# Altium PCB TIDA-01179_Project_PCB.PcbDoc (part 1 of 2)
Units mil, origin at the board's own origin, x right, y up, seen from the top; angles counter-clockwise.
Board outline 3149.61 x 2755.91 mil, 4 copper layers (Top Layer, 2nd Layer, 3rd layer, Bottom Layer), stack 51.6 mil thick; 141 components, 52 nets, 310 pads, 228 vias.
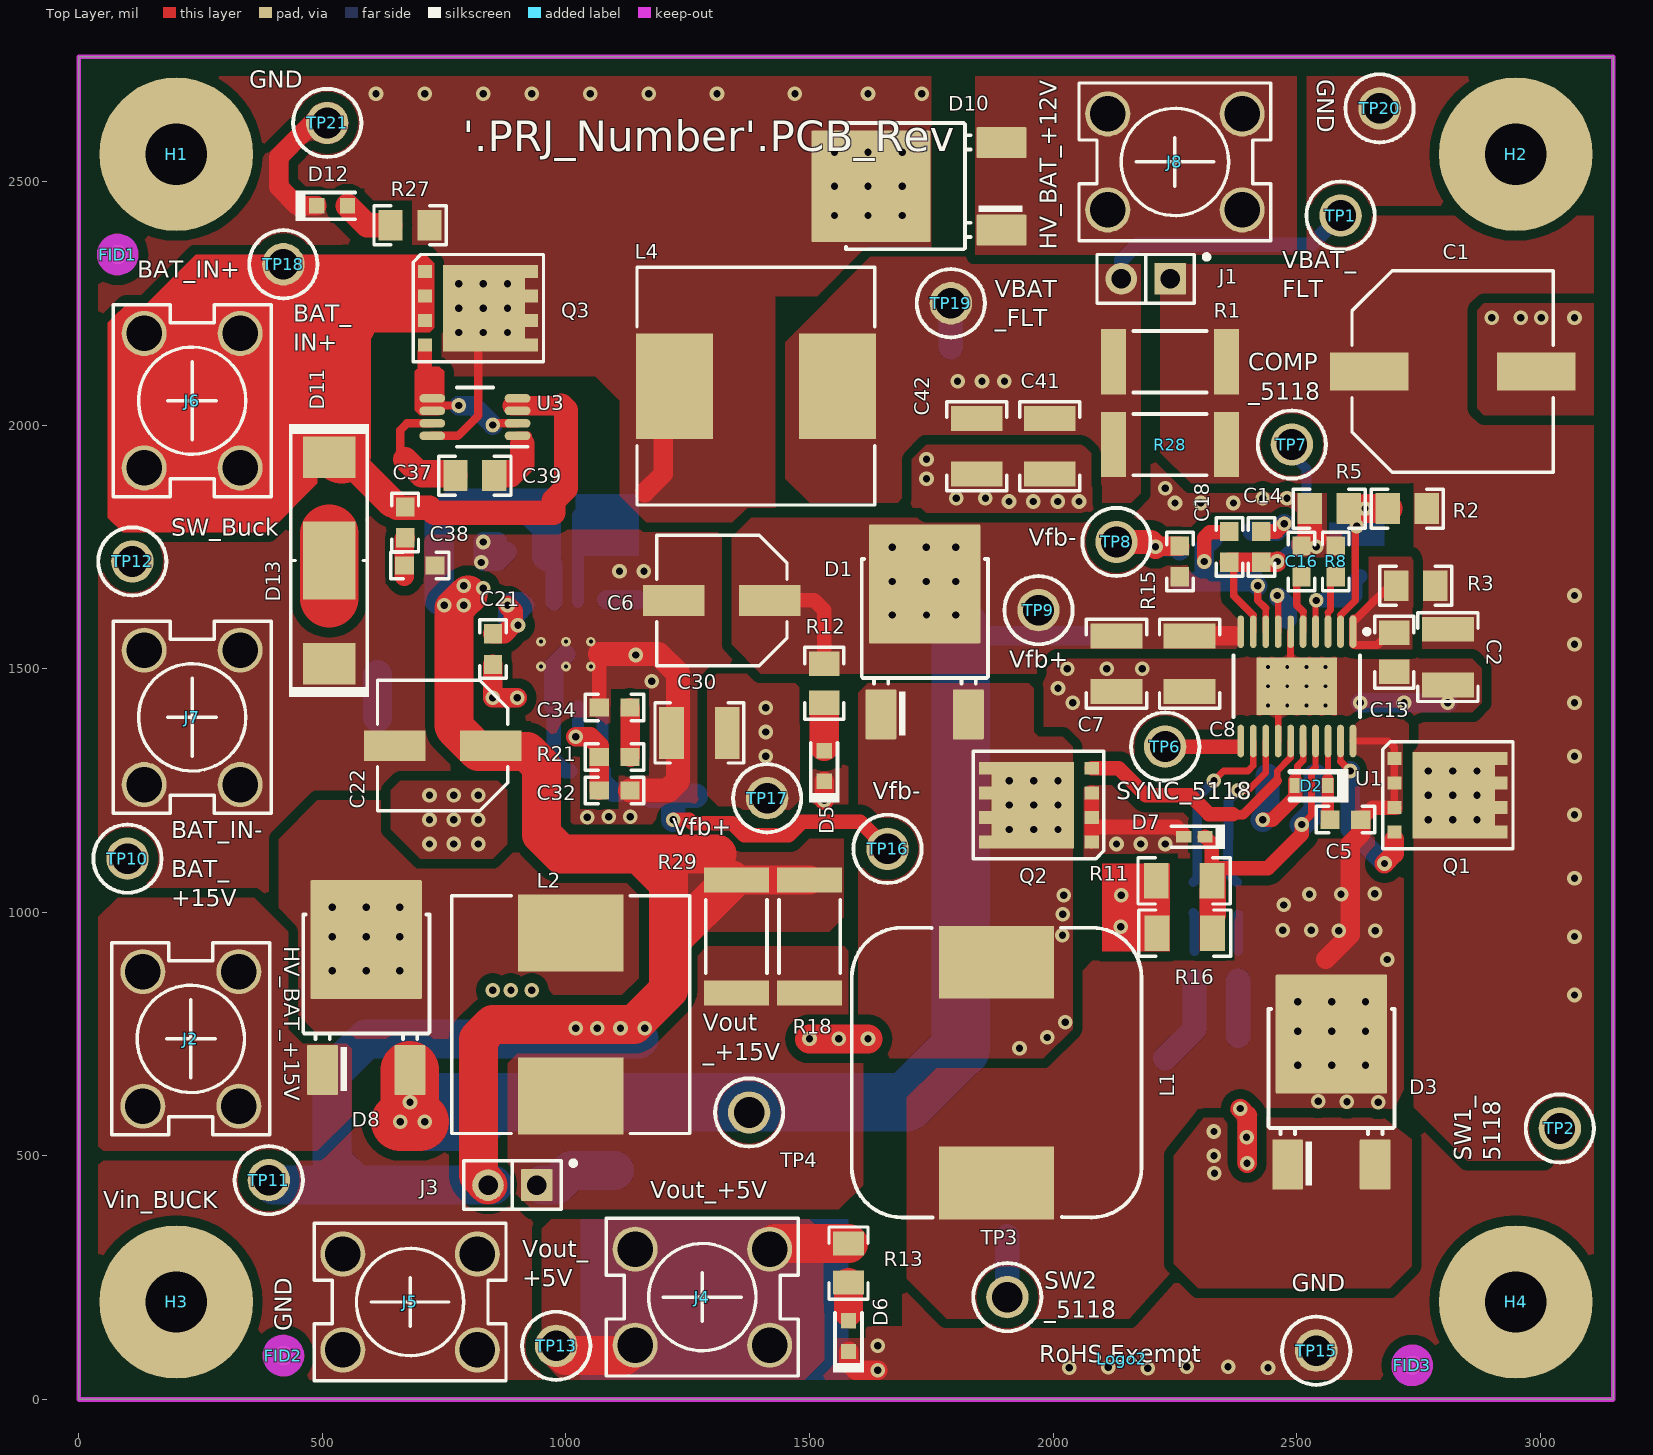
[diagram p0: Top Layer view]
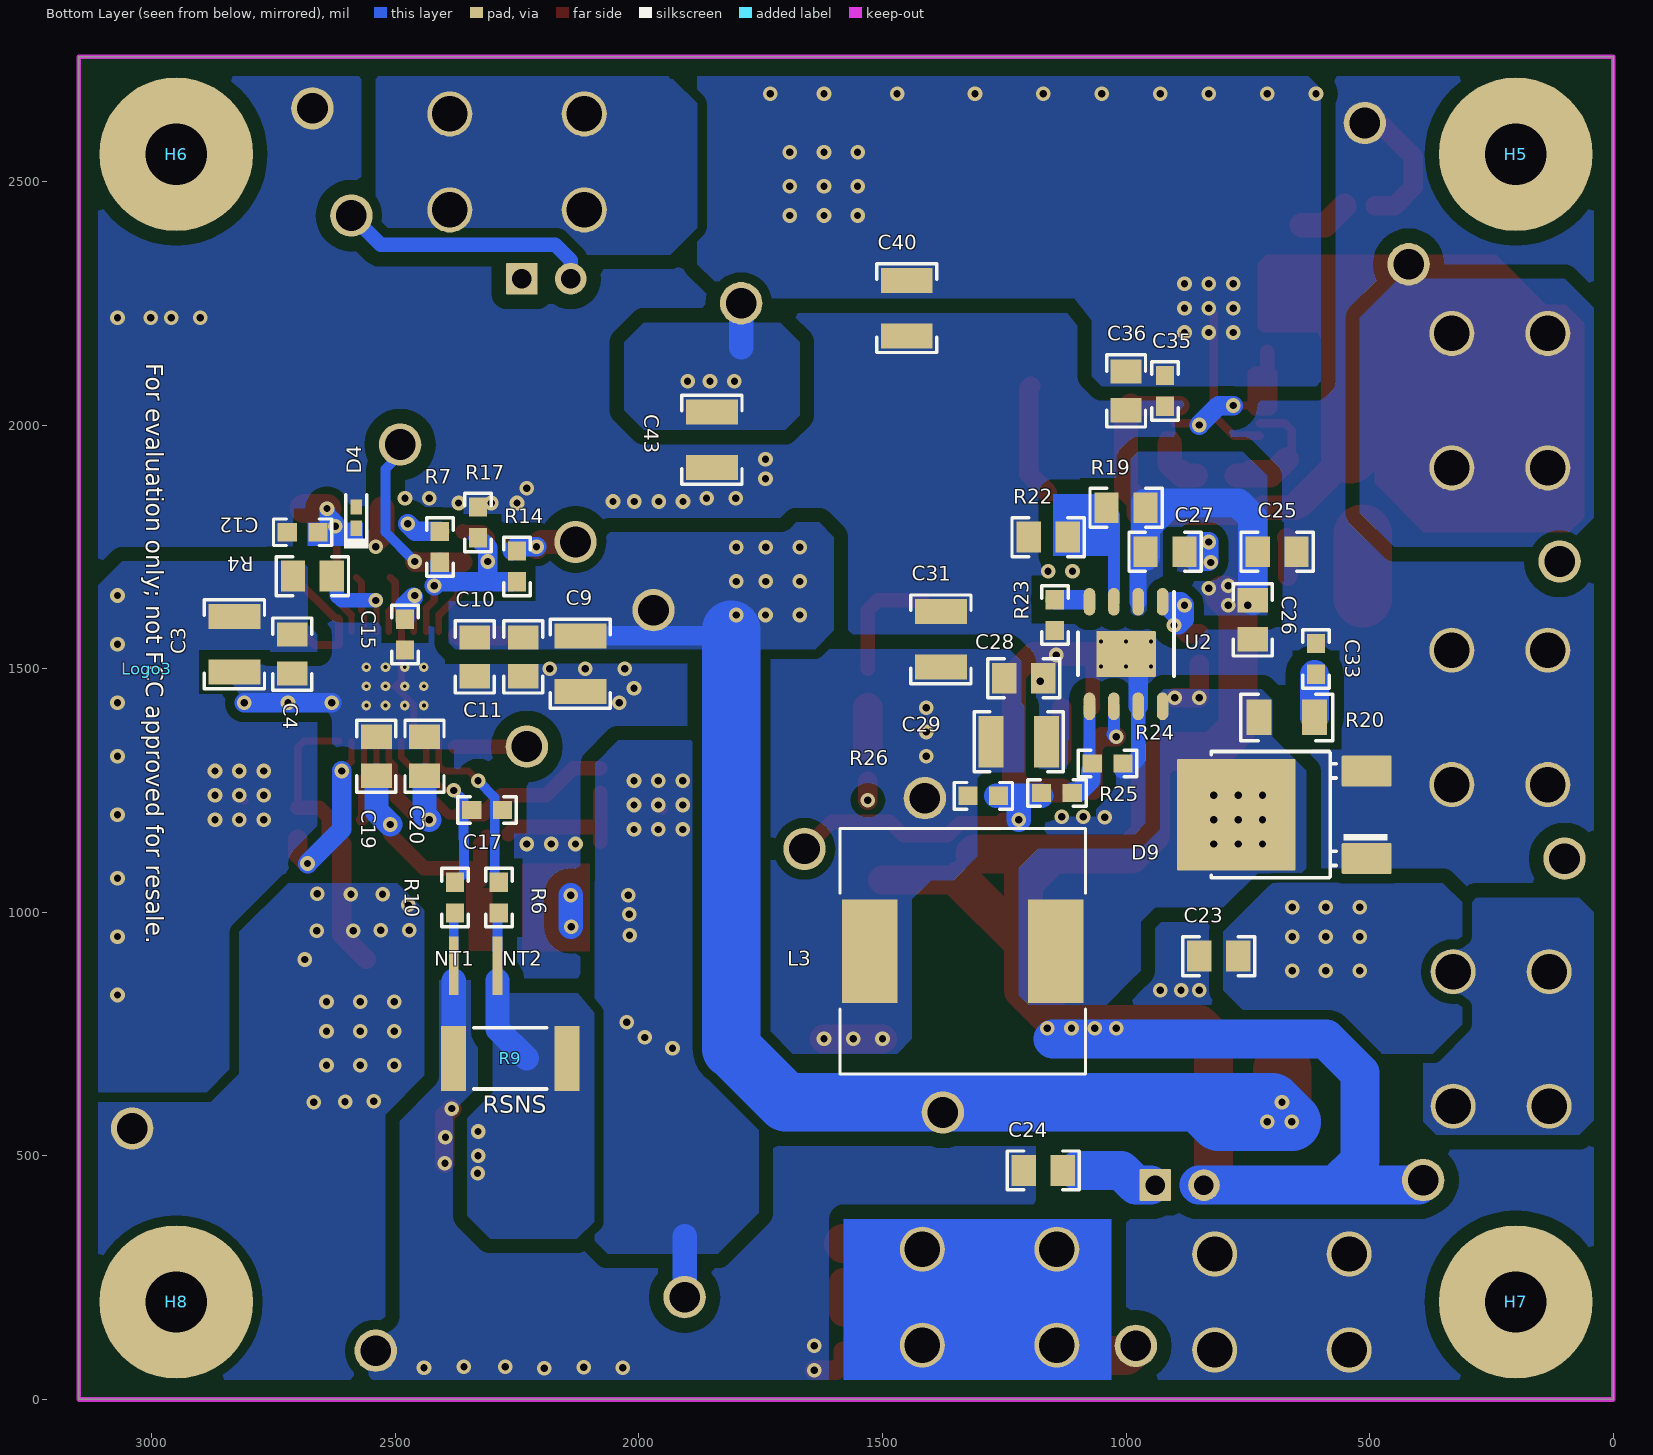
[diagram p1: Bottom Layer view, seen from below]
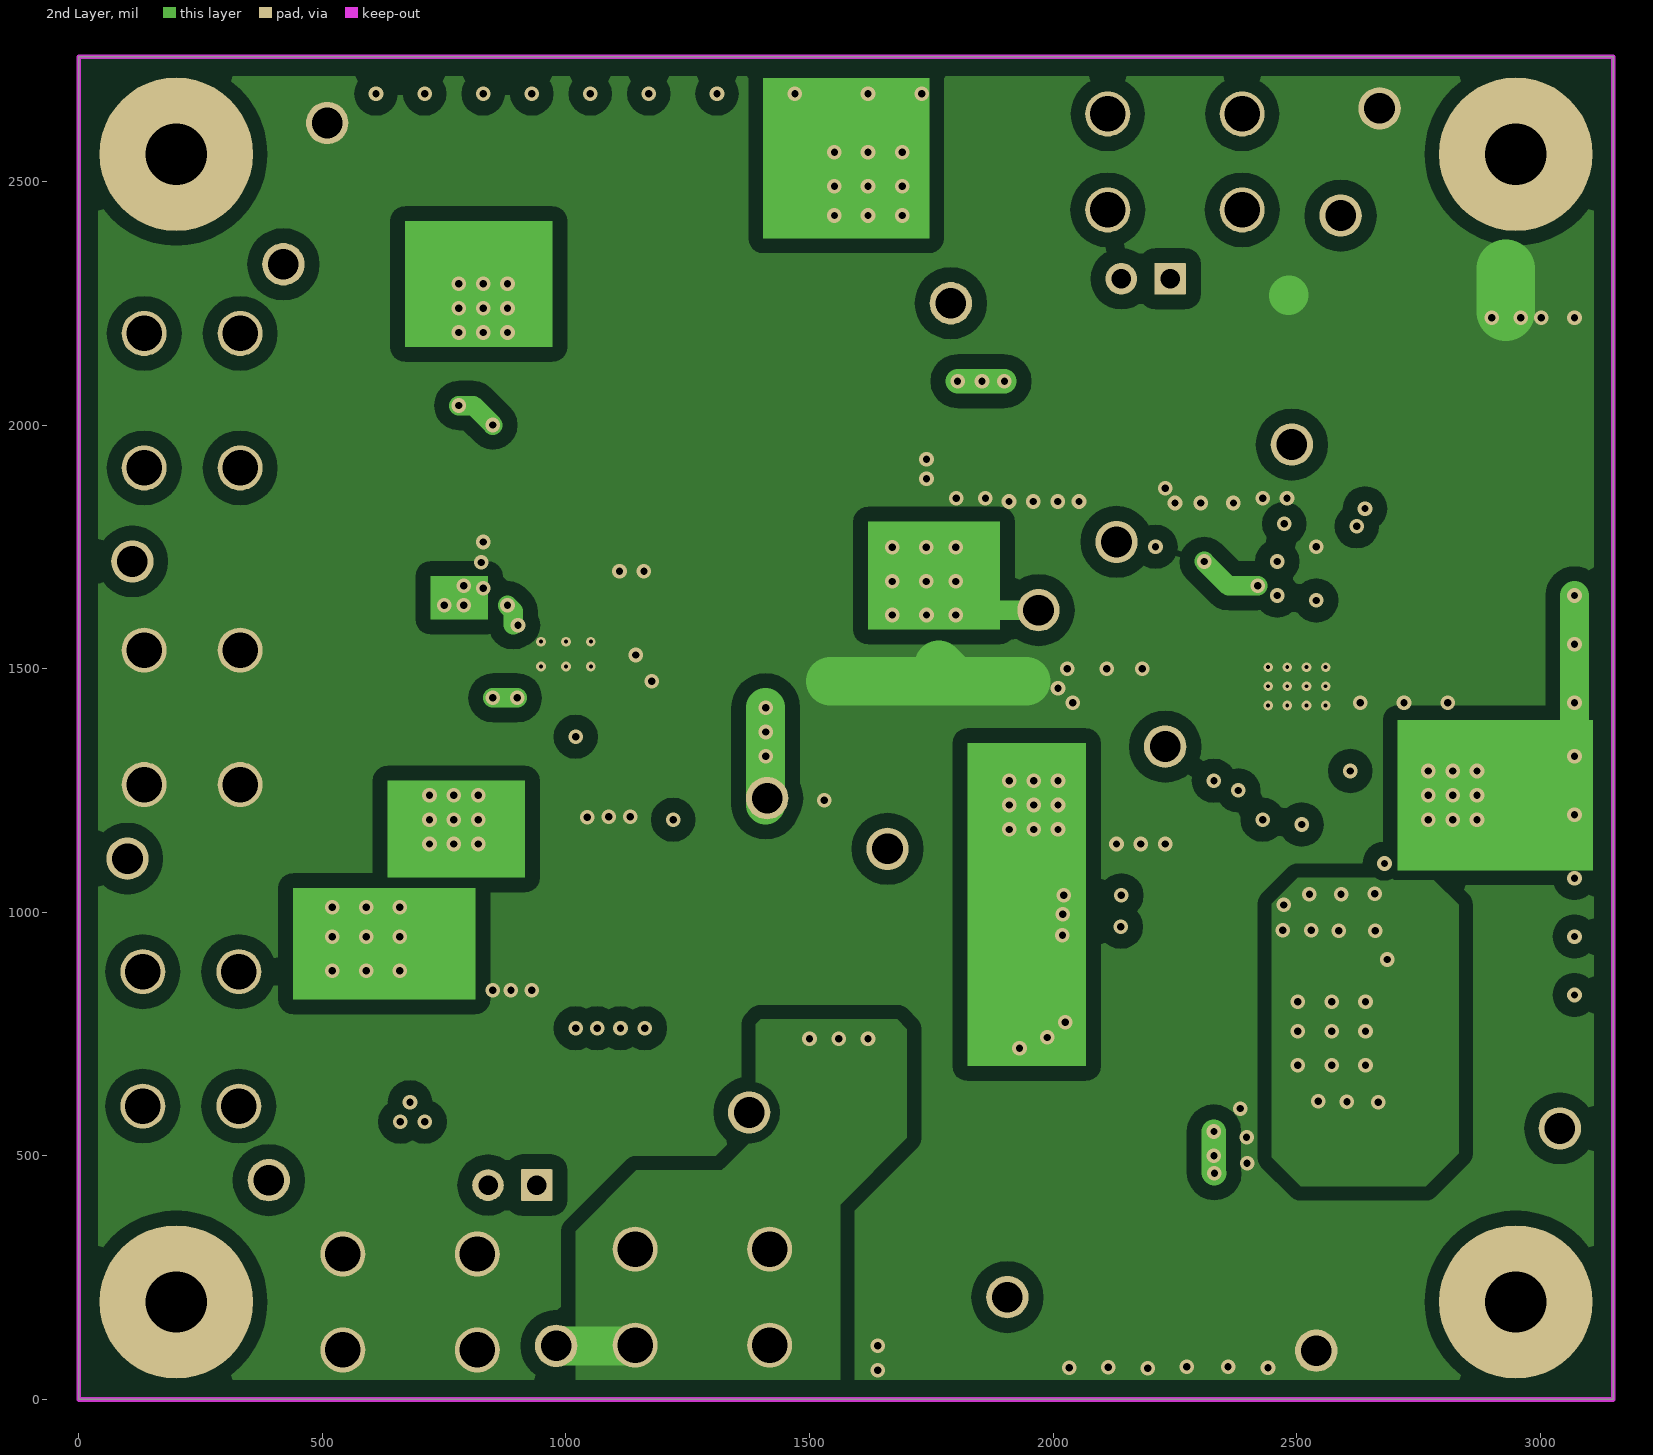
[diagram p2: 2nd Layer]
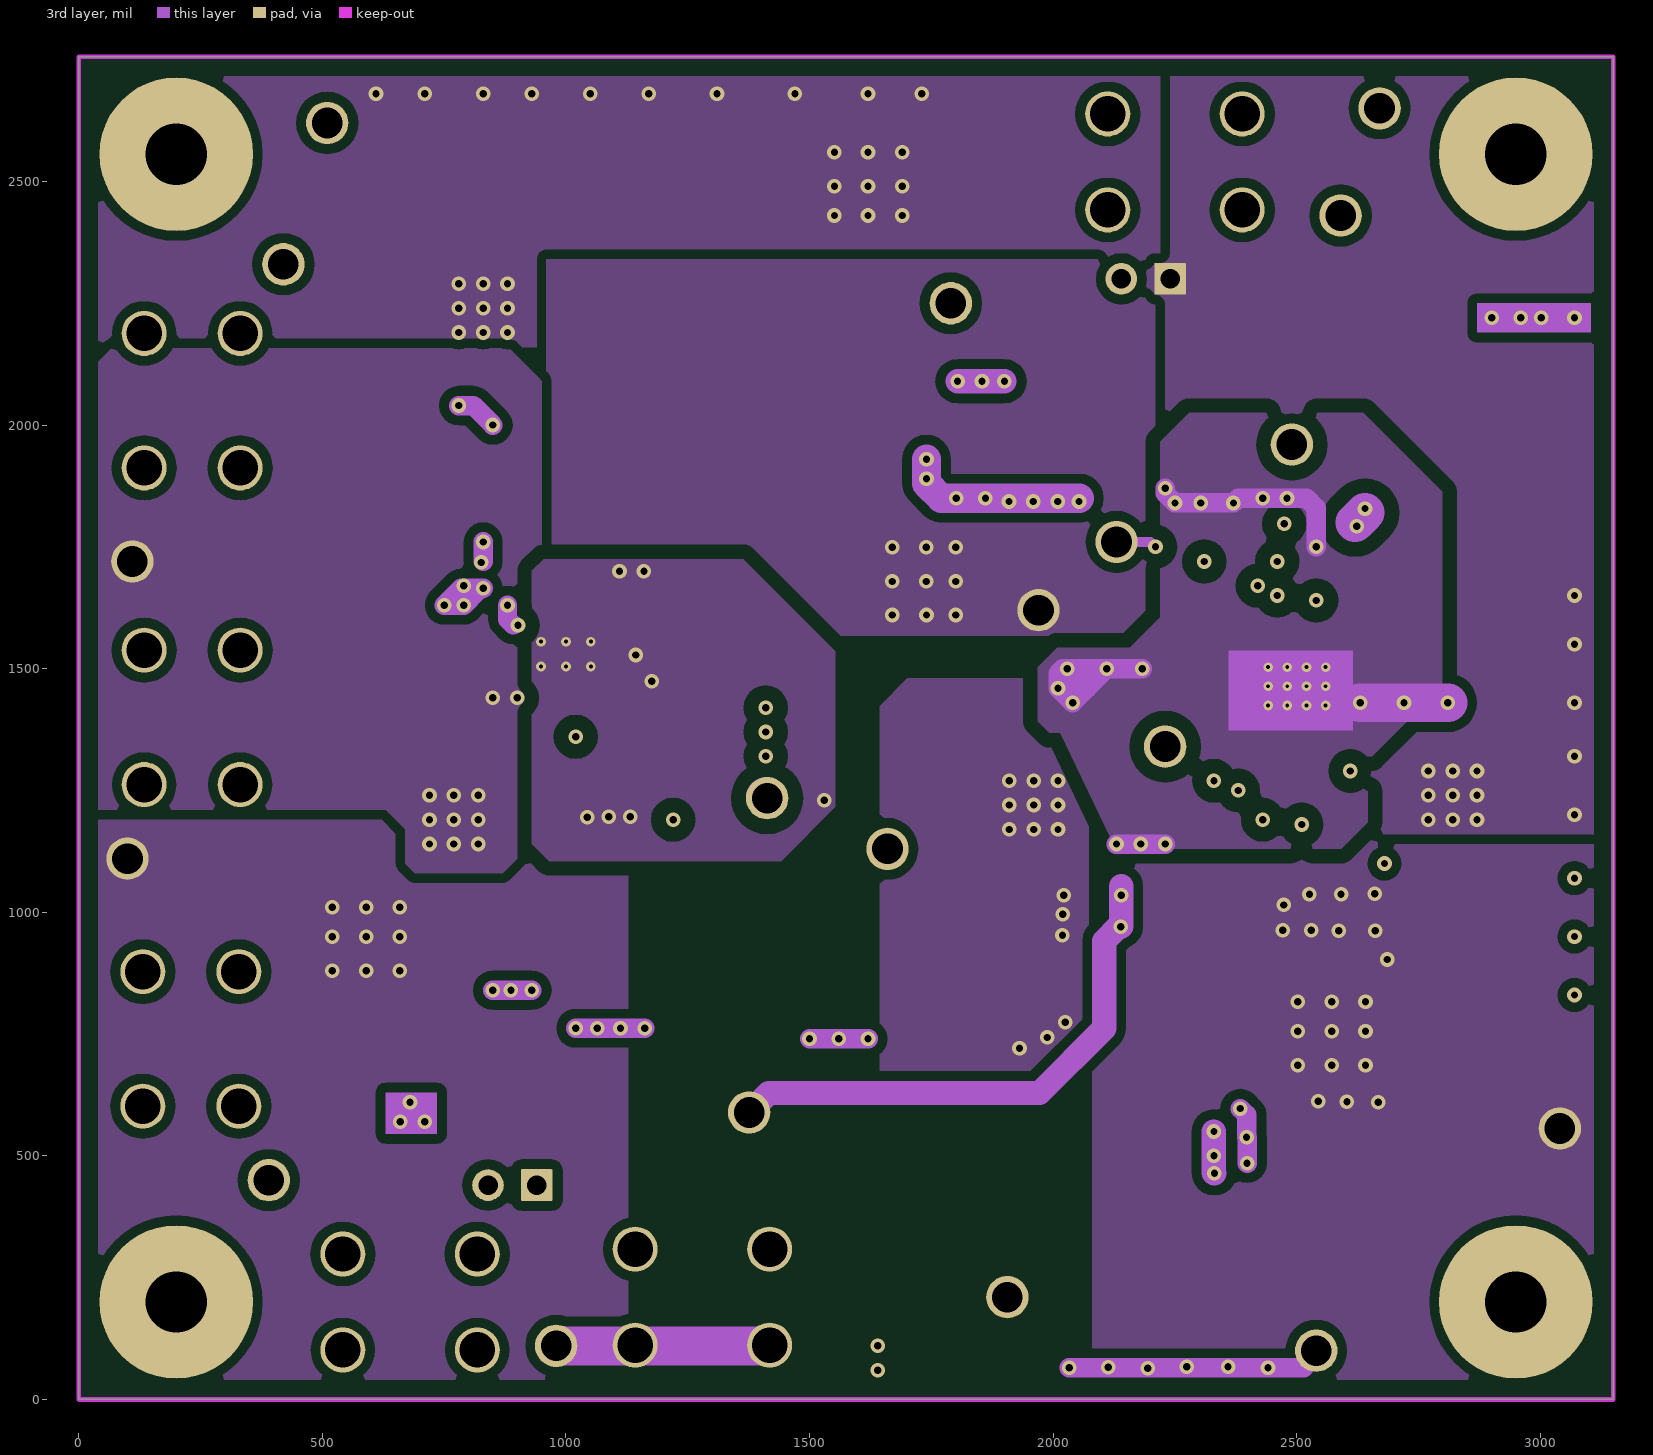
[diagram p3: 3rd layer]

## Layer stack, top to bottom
Top Solder: solder mask 0.4, Solder Resist, Dk 3.5
Top Layer: signal copper 1.4
Dielectric1: prepreg 5, FR-4, Dk 4.2
2nd Layer: signal copper 1.4
Dielectric 2: core 36, FR-4, Dk 4.2
3rd layer: signal copper 1.4
Dielectric 3: prepreg 5, FR-4, Dk 4.2
Bottom Layer: signal copper 1.4
Bottom Solder: solder mask 0.4, Solder Resist, Dk 3.5

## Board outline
0,0 3149.61,0 3149.61,2755.91 0,2755.91

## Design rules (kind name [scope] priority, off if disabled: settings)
AcuteAngle [All] p1: minimum=4.50000000000000E+0001 checktracksonly=FALSE
AssemblyTestPointUsage [All] p1: valid=2
BoardOutlineClearance BoardOutlineClearance_MountingHoles [OnCopper and InComponentClass('Mounting Holes')] p1: gap=40
BoardOutlineClearance BoardOutlineClearance_Poly [OnCopper and InPoly] p2: gap=15
BoardOutlineClearance [OnCopper and Not InComponentClass('Logo') and not InComponentClass('FiducialMark') and not InRegion(1000,500,4000,800)] p3: gap=40
Clearance Clearance_GNDPoly [(InNamedPolygon('2ND_LAYER_GND_P304') OR InNamedPolygon('3RD_LAYER_GND_P231') OR InNamedPolygon('3RD_LAYER_GND_P233') OR InNamedPolygon('BOTTOM_LAYER_GND_P240') OR InNamedPolygon('BOTTOM_LAYER_GND_P300'))] p1: gap=30
Clearance Clearance_Keepouts [((IsTrack Or IsArc) And Not InPoly) And IsFree and IsKeepOut vs ((IsTrack Or IsArc) And Not InPoly) And IsFree and IsKeepOut] p2: gap=0
Clearance Clearance_Poly [InPolygon] p3: gap=20
Clearance [All] p4: gap=7.5
ComponentClearance ComponentClearance_MountingHoles_FiducialMarks [InComponentClass('Mounting Holes') vs InComponentClass('FiducialMark')] p1: gap=50 collisioncheckmode=3 verticalgap=10 showdistances=FALSE
ComponentClearance ComponentClearance_Shunt [InComponentClass('Header') vs InComponentClass('Shunt')] p2: gap=0 collisioncheckmode=3 verticalgap=0 showdistances=FALSE
ComponentClearance ComponentClearance_Logo [InComponentClass('Logo')] p3: gap=50 collisioncheckmode=3 verticalgap=10 showdistances=FALSE
ComponentClearance ComponentClearance_ScrewToNut [(HasFootprint('NY PMS 440 0025 PH')) vs (HasFootprint('Keystone_1902C'))] p4: gap=5 collisioncheckmode=3 verticalgap=10 showdistances=FALSE
ComponentClearance ComponentClearance_MountingHoles [InComponentClass('Mounting Holes')] p5: gap=100 collisioncheckmode=3 verticalgap=100000 showdistances=FALSE
ComponentClearance ComponentClearance_SmallPassives [HasFootprint('0201*') or HasFootprint('0402*') or HasFootprint('0508') or HasFootprint('0603*') or HasFootprint('0612') or HasFootprint('0805*') or HasFootprint('0815*') or HasFootprint('0830*') or HasFootprint('1206*') or HasFootprint('1210*') or HasFootprint('1808*') or HasFootprint('1812*') or HasFootprint('1825*') or HasFootprint('2010*') or HasFootprint('2220*') or HasFootprint('2225*') or HasFootprint('2512*') or HasFootprint('2728*') or HasFootprint('3518*') vs HasFootprint('0201*') or HasFootprint('0402*') or HasFootprint('0508') or HasFootprint('0603*') or HasFootprint('0612') or HasFootprint('0805*') or HasFootprint('0815*') or HasFootprint('0830*') or HasFootprint('1206*') or HasFootprint('1210*') or HasFootprint('1808*') or HasFootprint('1812*') or HasFootprint('1825*') or HasFootprint('2010*') or HasFootprint('2220*') or HasFootprint('2225*') or HasFootprint('2512*') or HasFootprint('2728*') or HasFootprint('3518*')] p6: gap=14.96 collisioncheckmode=3 verticalgap=10 showdistances=FALSE
ComponentClearance ComponentClearance_THtoSMT [IsThruComponent vs IsSMTComponent] p7: gap=40 collisioncheckmode=3 verticalgap=30 showdistances=FALSE
ComponentClearance ComponentClearance_THtoTH [IsThruComponent vs IsThruComponent] p8: gap=30 collisioncheckmode=3 verticalgap=30 showdistances=FALSE
ComponentClearance [All] p9: gap=30 collisioncheckmode=3 verticalgap=10 showdistances=FALSE
DiffPairsRouting [All] p1: maxlimit=100 minlimit=10 mostfreqgap=10 toplayer_minwidth=15 toplayer_maxwidth=15 toplayer_prefwidth=15 midlayer1_minwidth=15 midlayer1_maxwidth=15 midlayer1_prefwidth=15 midlayer2_minwidth=15 midlayer2_maxwidth=15 midlayer2_prefwidth=15 bottomlayer_minwidth=15 bottomlayer_maxwidth=15 bottomlayer_prefwidth=15 maxuncoupledlength=1000
FabricationTestPointUsage TestPointUsage [All] p1: valid=2 allowmultiple=FALSE
FabricationTestpoint Testpoint [All] p1: side=3 testpointundercomponent=TRUE minsize=40 maxsize=100 preferedsize=60 minholesize=0 maxholesize=40 preferedholesize=32 testpointgrid=1 allowsidetop=TRUE allowsidebottom=TRUE usegrid=TRUE gridtolerance=0.01
FanoutControl Fanout_LCC [IsLCC] p1: bgadir=Out bgaviamode=Centered fanoutstyle=Auto fanoutdirection=Alternating viagrid=1 // Fanout_LCC (Default Rule)
FanoutControl Fanout_BGA [IsBGA] p2: bgadir=Out bgaviamode=Centered fanoutstyle=Auto fanoutdirection=Alternating viagrid=1 // Fanout_BGA (Default Rule)
FanoutControl Fanout_Default [All] p4: bgadir=Out bgaviamode=Centered fanoutstyle=Auto fanoutdirection=Alternating viagrid=1 // Fanout_Default (Default Rule)
FanoutControl Fanout_Small [(CompPinCount < 5)] p5: bgadir=Out bgaviamode=Centered fanoutstyle=Auto fanoutdirection=OutThenIn viagrid=1 // Fanout_Small (Default Rule)
HoleSize [All] p1: absolutevalues=TRUE maxlimit=251 minlimit=7.87 maxpercent=80.000 minpercent=20.000
MinimumAnnularRing MinimumAnnularRing_ThermalPadVias [IsVia and InAnyComponent] p1: minimumring=5.91
MinimumAnnularRing [All] p2: minimumring=7
MinimumSolderMaskSliver MinimumSolderMaskSliver_Via [IsVia] p1: minsoldermaskwidth=1.97
MinimumSolderMaskSliver MinimumSolderMaskSliver_Logo [InComponentClass('Logo') vs InComponentClass('Logo')] p2: minsoldermaskwidth=0.7
MinimumSolderMaskSliver [All] p3: minsoldermaskwidth=3.94
PlaneConnect [All] p1: planeconnectstyle=Direct reliefexpansion=10 reliefentries=4 reliefconductorwidth=10 reliefairgap=10
PolygonConnect [All] p1: connectstyle=Direct reliefconductorwidth=10 reliefentries=4 polygonreliefangle="90 Angle" airgapwidth=10
RoutingVias ThermalPadVias [IsVia and InAnyComponent] p1: holewidth=7.87 width=19.68 viastyle="Through Hole" minholewidth=7.87 minwidth=19.68 maxholewidth=12.99 maxwidth=23.62
RoutingVias [All] p2: holewidth=10 width=20 viastyle="Through Hole" minholewidth=7.87 minwidth=5 maxholewidth=40 maxwidth=65
SilkToBoardRegionClearance [Not ((IsComment or IsDesignator) And (Hide <> 'False')) and not InRegion(1000,500,4000,800)] p1:
SilkToSilkClearance SilkToSilkClearance_Pb-FreeLogo [(HasFootprint('Pb-Free_Overlay_Medium') OR HasFootprint('Pb-Free_Overlay_Small')) vs (HasFootprint('Pb-Free_Overlay_Medium') OR HasFootprint('Pb-Free_Overlay_Small'))] p1: silktosilkclearance=0
SilkToSilkClearance [All] p2: silktosilkclearance=4
SilkToSolderMaskClearance SilkToSolderMaskClearance_Via [IsVia] p1: minsilkscreentomaskgap=0 clearancetoexposedcopper=TRUE
SilkToSolderMaskClearance SilkToComponentPadClearance [IsPad and InAnycomponent] p2: minsilkscreentomaskgap=5 clearancetoexposedcopper=TRUE
SilkToSolderMaskClearance "Silk to Solder Mask Opening" [All] p3: minsilkscreentomaskgap=4 clearancetoexposedcopper=FALSE
SolderMaskExpansion SolderMaskExpansion_Vias [IsVia] p1: expansion=-20
SolderMaskExpansion [All] p2: expansion=1.97
Width [All] p1: maxlimit=200 minlimit=6 preferedwidth=10 checkconnectedcopper=TRUE
15 further rules are at their usual default settings.

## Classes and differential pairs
component class AssemblyNote: ZZ1 ZZ2 ZZ3 ZZ4
component class FiducialMark: FID1 FID2 FID3
component class TIDA-01179_Hardware: FID1 FID2 FID3 H1 H2 H3 H4 H5 H6 H7 H8 Logo2 Logo3 ZZ1 ZZ2 ZZ3 ZZ4
component class "Mounting Holes": H1 H2 H3 H4
component class Header: J1 J3
component class TIDA-01179_DCDC_Converters: C1 C2 C3 C4 C5 C6 C7 C8 C9 C10 C11 C12 C13 C14 C15 C16 C17 C18 C19 C20 C21 C22 C23 C24 C25 C26 C27 C28 C29 C30 C31 C32 C33 C34 D1 D2 D3 D4 D5 D6 D7 D8 D9 J1 J2 J3 J4 J5 L1 L2 L3 NT1 NT2 Q1 Q2 R1 R2 R3 R4 R5 R6 R7 R8 R9 R10 R11 R12 R13 R14 R15 R16 R17 R18 R19 R20 R21 R22 R23 R24 R25 R26 R28 R29 TP1 TP2 TP3 TP4 TP6 TP7 TP8 TP9 TP10 TP11 TP12 TP13 TP15 TP16 TP17 U1 U2
component class TIDA-01179_Reverse_Polarity_Protection: C35 C36 C37 C38 C39 C40 C41 C42 C43 COMP D10 D11 D12 D13 GND J6 J7 J8 L4 Q3 R27 TP18 TP19 TP20 TP21 U3

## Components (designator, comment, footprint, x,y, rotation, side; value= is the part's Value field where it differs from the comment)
C1 "EEE-FK1H151P" SM_RADIAL_G 2820,2110 r0 top
C2 "GRM32DR71H335KA88L" 1210_220 2810.24,1523.7 r270 top
C3 "GRM32DR71H335KA88L" 1210_220 2830,1550 r270 bottom
C4 "GRM219R71H333KA01D" 0805_HV 2711.46,1530 r270 bottom
C5 "GRM188R71E104KA01D" 0603 2600,1190 r0 top
C6 "EEE-FK1V101XP" SM_RADIAL_D8 1320,1640 r180 top
C7 "GRM32ER71E226KE15L" 1210_270 2130,1510 r270 top
C8 "GRM32ER71E226KE15L" 1210_270 2280,1510 r270 top
C9 "GRM32ER71E226KE15L" 1210_270 2120,1510 r270 bottom
C10 "GRM219R71E224KA01D" 0805_HV 2337.05,1524.02 r270 bottom
C11 "GRM219R71E224KA01D" 0805_HV 2237.05,1524.02 r270 bottom
C12 "GRM188R71E104KA01D" 0603 2690,1780 r0 bottom
C13 "GRM21BR71H104KA01L" 0805_HV 2700.24,1533.7 r270 top
C14 "GRM188R71E184KA88D" 0603 2427.24,1750 r270 top
C15 "GRM188R71E104KA01D" 0603 2480,1570 r270 bottom
C16 "GRM188R71H391KA01D" 0603 2510,1720 r90 top
C17 "GRM1885C1H101JA01D" 0603 2311.46,1210 r0 bottom
C18 "GCM1885C1H471JA16D" 0603 2361.57,1750 r270 top
C19 "GRM21BR71E105KA99L" 0805_HV 2538.62,1320 r90 bottom
C20 "GRM21BR71E105KA99L" 0805_HV 2440,1320 r90 bottom
C21 "GRM188R71E104KA01D" 0603 850,1540 r90 top
C22 "EEE-FK1V470P" SM_RADIAL_D 747,1342 r180 top
C23 "GRM21BZ71E106KE15L" 0805_HV 810,910 r0 bottom
C24 "GRM21BZ71E106KE15L" 0805_HV 1170,470 r0 bottom
C25 "GRM21BR71E475KA73L" 0805_HV 690,1740 r180 bottom
C26 "GRM21BR71E475KA73L" 0805_HV 740,1600 r270 bottom
C27 "GRM219R71E473KA01D" 0805_HV 920,1740 r180 bottom
C28 "GRM219R71E473KA01D" 0805_HV 1210,1480 r180 bottom
C29 "GRM32ER61C476ME15L" 1210_270 1220,1350 r180 bottom
C30 "GRM32ER61C476ME15L" 1210_270 1274,1368 r180 top
C31 "GRM32ER61C476ME15L" 1210_270 1380,1560 r90 bottom
C32 "GRM1885C1H470JA01D" 0603 1100,1250 r0 top
C33 "GRM188R71H681KA01D" 0603 610,1520 r90 bottom
C34 "GCM188R71H472KA37D" 0603 1100,1420 r180 top
C35 "GRM188R71H104KA93D" 0603 920,2070 r270 bottom
C36 "GRM21BR71H105KA12L" 0805_HV 1000,2070 r270 bottom
C37 "GRM188R71H104KA93D" 0603 670,1800 r270 top
C38 "GRM188R71H104KA93D" 0603 700,1711.46 r0 top
C39 "C2012X7R1H225K125AC" 0805_HV 813.15,1896.3 r0 top
C40 "GRM32ER71H106KA12L" 1210_270 1450,2240 r270 bottom
C41 "GRM32ER71H106KA12L" 1210_270 1993.15,1956.3 r270 top
C42 "GRM32ER71H106KA12L" 1210_270 1843.15,1956.3 r270 top
C43 "GRM32ER71H106KA12L" 1210_270 1850,1970 r270 bottom
D1 "12CWQ06FNPBF" DPAK 1736.3,1540 r90 top
D2 "CDBU0245" SOD-523F 2530,1260 r180 top
D3 "VS-12CWQ10FNPBF" DPAK 2571,616 r90 top
D4 "BZT52C12T-7" SOD-523 2580,1810 r90 bottom
D5 "150060GS75000" WL-SMCW_GREEN 1530,1300 r90 top
D6 "150060GS75000" WL-SMCW_GREEN 1580,130 r90 top
D7 "BZT52C12T-7" SOD-523 2290,1154.57 r180 top
D8 "12CWQ04FNPBF" DPAK 590,810 r90 top
D9 "MBRD835LT4G" DPAK 640,1200 r0 bottom
D10 "6CWQ06FNPBF" DPAK 1760,2490 r180 top
D11 "SMBJ26A-13-F" SMB 514,1847 r270 top
D12 "150060GS75000" WL-SMCW_GREEN 520,2450 r0 top
D13 "SMBJ14A-13-F" SMB 514,1597 r90 top
FID1 "Fiducial" Fiducial10-20 80,2350 r0 top
FID2 "Fiducial" Fiducial10-20 420,90 r0 top
FID3 "Fiducial" Fiducial10-20 2736.85,70 r0 top
H1 "NY PMS 440 0025 PH" "NY PMS 440 0025 PH" 200,2555.91 r0 top locked
H2 "NY PMS 440 0025 PH" "NY PMS 440 0025 PH" 2949.61,2555.91 r0 top locked
H3 "NY PMS 440 0025 PH" "NY PMS 440 0025 PH" 200,200 r0 top locked
H4 "NY PMS 440 0025 PH" "NY PMS 440 0025 PH" 2949.61,200 r0 top locked
H5 "1902C" Keystone_1902C 200,2555.91 r180 bottom locked
H6 "1902C" Keystone_1902C 2949.61,2555.91 r180 bottom locked
H7 "1902C" Keystone_1902C 200,200 r180 bottom locked
H8 "1902C" Keystone_1902C 2949.61,200 r180 bottom locked
J1 "HTSW-102-07-G-S" Samtec_HTSW-102-07-G-S 2190,2300 r180 top
J2 "7693" 7693 230,740 r0 top
J3 "HTSW-102-07-G-S" Samtec_HTSW-102-07-G-S 890,440 r180 top
J4 "7693" 7693 1280,210 r90 top
J5 "7693" 7693 680,200 r90 top
J6 "7693" 7693 232.76,2050 r0 top
J7 "7693" 7693 232.76,1400 r0 top
J8 "7693" 7693 2250,2540 r90 top
L1 "MSS1583-123MEB" MSS1583 1884,671 r90 top
L2 "MSS1260-472MLB" MSS1260 1010,790 r270 top
L3 "SRR1260A-6R1Y" SRR1260A 1335,920 r0 bottom
L4 "MSS1260-472MLB" MSS1260 1390,2080 r0 top
Logo2 "EU RoHS Exempt Logo" EURoHS_Exempt_60mil 2141,84 r0 top
Logo3 "FCC disclaimer" FCC_disclaimer 3010,1500 r270 bottom
NT1 "Net-Tie" Net-Tie_20milWide_60milLong 2380,890 r270 bottom net-tie
NT2 "Net-Tie" Net-Tie_20milWide_60milLong 2290,890 r270 bottom net-tie
Q1 "CSD18563Q5A" TRANS_NexFET_Q5A 2810,1240 r0 top
Q2 "CSD18563Q5A" TRANS_NexFET_Q5A 1970,1220 r180 top
Q3 "CSD18563Q5A" TRANS_NexFET_Q5A 820,2240 r0 top
R1 "CRCW25120000Z0EGHP" 2512 2240,2130 r0 top
R2 "CRCW080533K2FKEA" 0805_HV 2726.61,1828.54 r0 top
R3 "CRCW080510R0FKEA" 0805_HV 2744,1670 r0 top
R4 "CRCW0805100KFKEA" 0805_HV 2670,1690 r0 bottom
R5 "CRCW080571K5FKEA" 0805_HV 2566.61,1828.54 r0 top
R6 "CRCW06030000Z0EA" 0603 2287.4,1030 r270 bottom
R7 "CRCW06037K50FKEA" 0603 2408.54,1750 r270 bottom
R8 "CRCW060316K9FKEA" 0603 2580,1720 r270 top
R9 "CRA2512-FZ-R015ELF" 2512 2264,700 r180 bottom
R10 "CRCW06030000Z0EA" 0603 2377.4,1030 r270 bottom
R11 "CRCW1206300RJNEA" 1206 2268.7,1064.57 r180 top
R12 "CRCW080512K0JNEA" 0805_HV 1530,1470 r90 top
R13 "CRCW08052K00FKEA" 0805_HV 1580,280 r90 top
R14 "CRCW06035K11FKEA" 0603 2250,1710 r270 bottom
R15 "CRCW060310R0FKEA" 0603 2260,1720 r270 top
R16 "CRCW1206300RJNEA" 1206 2270,957 r180 top
R17 "CRCW0603464RFKEA" 0603 2330,1800 r270 bottom
R18 "CRCW25120000Z0EGHP" 2512 1500,950 r90 top
R19 "CRCW0805825KFKEA" 0805_HV 1000,1830 r180 bottom
R20 "CRCW12065R60JNEA" 1206 670,1400 r0 bottom
R21 "CRCW060316K9FKEA" 0603 1100,1318.54 r180 top
R22 "CRCW0805110KFKEA" 0805_HV 1160,1770 r180 bottom
R23 "CRCW0603249KFKEA" 0603 1146.14,1610 r90 bottom
R24 "CRCW060310K0FKEA" 0603 1038,1305 r0 bottom
R25 "CRCW060353K6FKEA" 0603 1142,1245 r0 bottom
R26 "CRCW060340R2FKEA" 0603 1293,1239 r0 bottom
R27 "CRCW08059K10JNEA" 0805_HV 680,2410 r0 top
R28 "CRCW25120000Z0EGHP" 2512 2240,1960 r0 top
R29 "CRCW25120000Z0EGHP" 2512 1350,950 r90 top
TP1 "5005" Keystone5005 2590,2430 r0 top
TP2 "5122" Keystone5122 3040,556.19 r0 top
TP3 "5122" Keystone5122 1906,210 r0 top
TP4 "5005" Keystone5005 1376,589 r0 top
TP6 "5122" Keystone5122 2230,1340 r0 top
TP7 "5122" Keystone5122 2490,1960 r0 top
TP8 "5122" Keystone5122 2130,1760 r0 top
TP9 "5005" Keystone5005 1970,1620 r0 top
TP10 "5005" Keystone5005 100,1110 r0 top
TP11 "5005" Keystone5005 390,450 r0 top
TP12 "5122" Keystone5122 110,1720 r0 top
TP13 "5005" Keystone5005 980,110 r0 top
TP15 "5006" Keystone5006 2540,100 r0 top
TP16 "5122" Keystone5122 1660,1130 r0 top
TP17 "5005" Keystone5005 1413,1234 r0 top
TP18 "5005" Keystone5005 420,2330 r0 top
TP19 "5005" Keystone5005 1790,2250 r0 top
TP20 "5006" Keystone5006 2670,2650 r0 top
TP21 "5006" Keystone5006 510,2620 r0 top
U1 "LM5118Q1MH/NOPB" MXA20A_N 2500.24,1463.7 r270 top
U2 "TPS54540QDDARQ1" DDA0008E_N 1000,1530 r270 bottom
U3 "LM74610QDGKRQ1" DGK0008A_N 813.15,2016.3 r180 top
ZZ1 "This Assembly Note is for PCB labels only" AssemblyNoteLabel 185,3938 r0 top
ZZ2 "These assemblies are ESD sensitive, ESD precautions shall be observed." AssemblyNote 185,3829.11 r0 top
ZZ3 "These assemblies must be clean and free from flux and all contaminants. Use of no clean flux is not acceptable." AssemblyNote 185,3740.56 r0 top
ZZ4 "These assemblies must comply with workmanship standards IPC-A-610 Class 2, unless otherwise specified." AssemblyNote 185,3652 r0 top

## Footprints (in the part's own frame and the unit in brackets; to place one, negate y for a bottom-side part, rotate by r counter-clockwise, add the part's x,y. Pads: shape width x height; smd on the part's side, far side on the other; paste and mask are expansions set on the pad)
0603 [mm] "0603 from SM-752 data"
  rect 1x0.95 smd: 1(-0.8,0) 2(0.8,0)
  silkscreen extent -1.52,-0.69 1.52,0.69, body extent -0.87,-0.47 0.87,0.47, height 1
0805_HV [mil] "0805 with 30mil clearance between pads"
  rect 50x63 smd: 1(-40,0) 2(40,0)
  silkscreen extent -74,-40 74,40, body extent -43,-29 43,29, height 57
1206 [mm] "1206 from SM-752 data"
  rect 1.3x1.85 smd: 1(-1.45,0) 2(1.45,0)
  silkscreen extent -2.4,-1.21 2.4,1.21, body extent -1.7,-0.9 1.7,0.9, height 1.35
1210_220 [mm] "1210"
  rect 1.3x2.7 smd: 1(-1.45,0) 2(1.45,0)
  silkscreen extent -2.32,-1.57 2.32,1.57, body extent -1.7,-1.35 1.7,1.35, height 2.2
1210_270 [mm] "1210"
  rect 1.3x2.7 smd: 1(-1.45,0) 2(1.45,0)
  silkscreen extent -2.32,-1.57 2.32,1.57, body extent -1.7,-1.35 1.7,1.35, height 2.7
2512 [mm] "Chip Resistor, Body 6.3x3.2mm, IPC Medium Density"
  rect 1.3x3.4 smd: 1(-2.95,0) 2(2.95,0)
  silkscreen extent -1.9,-1.6 1.9,1.6, body extent -3.22,-1.67 3.22,1.67, height 0.71
7693 [mm] "Keystone Electronics 7693 recommended land pattern"
  round 2.35 hole 1.85: 1(-2.502,3.505) 2(2.502,3.505) 3(-2.502,-3.505) 4(2.502,-3.505)
  silkscreen extent -4.11,-5 4.11,5, body extent -3.95,-3.94 3.95,3.96, height 8.86
AssemblyNote [mil] "Assembly Note"
AssemblyNoteLabel [mil] "Assembly Note for PCB Labels"
DDA0008E_N [mm]
  rrect100% 1.45x0.6 smd: 1(-2.725,1.905) 2(-2.725,0.635) 3(-2.725,-0.635) 4(-2.725,-1.905) 5(2.725,-1.905) 6(2.725,-0.635) 7(2.725,0.635) 8(2.725,1.905)
  rrect4% 2.4x3.1 smd: 9(0,0)
  silkscreen extent -3.22,-2.5 1.15,2.5, body extent -3.01,-2.45 3.01,2.45, height 1.7
DGK0008A_N [mm] "TSOP, 8-Leads, Body 3x3mm, Pitch 0.65mm, IPC Medium Density"
  oval 1.35x0.45 smd: 1(-2.225,0.975) 2(-2.225,0.325) 3(-2.225,-0.325) 4(-2.225,-0.975) 5(2.225,-0.975) 6(2.225,-0.325) 7(2.225,0.325) 8(2.225,0.975)
  silkscreen extent -2.75,-1.55 0.95,1.55, body extent -2.45,-1.5 2.45,1.5, height 0.96
DPAK [mm] "D-PAK, 3-Pads, Body 6.22x6.73mm (max), TO-252AA using nominal STEP model"
  rrect6% 2.6x1.6 smd: 1(-3.4,2.28) 3(-3.4,-2.28)
  rrect2% 6.2x5.8 smd paste-2.9: 4(3.4,0)
  silkscreen extent -4.5,-3.3 4.7,3.28, body extent -3.86,-3.29 5.84,3.29, height 2.48
EURoHS_Exempt_60mil [mil] "EU RoHS Exempt symbol"
FCC_disclaimer [mil]
Fiducial10-20 [mm]
  round 1 smd mask+0.5: 1(0,0)
  Top Layer keep-out circle w1.178: c0,0 r0.5
Keystone5005 [mil] "Keystone Compact loops"
  round 87 hole 63: 1(0,0)
  silkscreen extent -70,-70 70,70, body extent -63,-63 62,63, height 225
Keystone5006 [mil] "Keystone Compact loops"
  round 87 hole 63: 1(0,0)
  silkscreen extent -70,-70 70,70, body extent -63,-63 62,63, height 225
Keystone5122 [mil] "Keystone Compact loops"
  round 87 hole 63: 1(0,0)
  silkscreen extent -70,-70 70,70, body extent -63,-63 62,63, height 225
Keystone_1902C [mil] "Hex Standoff, 4-40 threaded, nylon"
  round 1 on Mech4: 0(0,0)
  body extent -145,-126 146,126, height 501
MSS1260 [mm]
  rect 4x5.5 smd: 1(-4.25,0) 2(4.25,0)
  silkscreen extent -6.2,-6.2 6.2,6.2, body extent -6.15,-6.15 6.15,6.15, height 6.25
MSS1583 [mm] "Coilcraft recommended land pattern"
  rect 3.8x6 smd: 1(-5.75,0) 2(5.75,0)
  silkscreen extent -7.55,-7.55 7.55,7.55, body extent -7.55,-7.55 7.55,7.55, height 9.05
MXA20A_N [mm] "TSOP, 20-Leads, Body 6.5x4.4mm, Pitch 0.65mm, Exposed Pad, IPC Medium Density"
  oval 1.7x0.35 smd: 1(-2.85,2.925) 2(-2.85,2.275) 3(-2.85,1.625) 4(-2.85,0.975) 5(-2.85,0.325) 6(-2.85,-0.325) 7(-2.85,-0.975) 8(-2.85,-1.625) 9(-2.85,-2.275) 10(-2.85,-2.925) 11(2.85,-2.925) 12(2.85,-2.275) 13(2.85,-1.625) 14(2.85,-0.975) 15(2.85,-0.325) 16(2.85,0.325) 17(2.85,0.975) 18(2.85,1.625) 19(2.85,2.275) 20(2.85,2.925)
  rect 3x4.2 smd: 21(0,0)
  silkscreen extent -2.97,-3.3 1.6,3.78, body extent -2.25,-3.3 2.25,3.3, height 1.1
Net-Tie_20milWide_60milLong [mil] "20mil net tie, no solder mask opening, no solder paste"
  rect 60x20 smd paste-10 mask-10: 1(-30,0) 2(30,0)
"NY PMS 440 0025 PH" [mm] "4-40 nylon screw and mounting hole"
  round 8 hole 3.2: 1(0,0)
  body extent -3.3,-3.3 3.3,3.3, height 2.69
Samtec_HTSW-102-07-G-S [mm] "Samtec 100mil, 1x2, 230 mil above insulator"
  rrect6% 1.65x1.65 hole 1.016: 1(-1.27,0)
  round 1.65 hole 1.016: 2(1.27,0)
  silkscreen extent -3.3,-1.27 2.54,1.27, body extent -2.54,-1.27 2.54,1.27, height 8.38
SM_RADIAL_D [mm] "6.3 x 5.8mm:  Panasonic D"
  rect 3.2x1.6 smd: 1(-2.5,0) 2(2.5,0)
  silkscreen extent -3.4,-3.4 3.4,3.4, body extent -3.4,-3.4 3.4,3.4, height 6.1
SM_RADIAL_D8 [mm] "6.3 x 7.7mm:  Panasonic D8"
  rect 3.2x1.6 smd: 1(-2.5,0) 2(2.5,0)
  silkscreen extent -3.4,-3.4 3.4,3.4, body extent -3.4,-3.4 3.4,3.4, height 8.01
SM_RADIAL_G [mm] "10 x 10.2mm:  Panasonic G"
  rect 4.1x2 smd: 1(-4.35,0) 2(4.35,0)
  silkscreen extent -5.25,-5.25 5.25,5.25, body extent -5.25,-5.25 5.25,5.25, height 10.5
SMB [mil] "Molded Diode, 2-Leads, Body 5.4x3.6mm, IPC Medium Density, based on OnSemi component dimensions"
  rect 85x107.99 smd: 1(-87.01,0) 2(87.01,0)
  silkscreen extent -155,-82 125,82, body extent -106,-71 106,71, height 91
SOD-523 [mm] "NXP Semiconductor recommended land pattern, nominal STEP model"
  rect 0.8x0.6 smd paste-0.05: 1(-0.55,0) 2(0.55,0)
  silkscreen extent -1.6,-0.63 1.2,0.64, body extent -0.8,-0.4 0.8,0.4, height 0.72
SOD-523F [mm] "COMCHIP"
  rect 0.6x0.8 smd paste-0.05: 1(-0.85,0) 2(0.85,0)
  silkscreen extent -1.92,-0.87 1.1,0.87, body extent -0.9,-0.5 0.9,0.5, height 0.85
SRR1260A [mil] "Bourns UL"
  rect 114x213 smd: 1(-191,0) 2(191,0)
  silkscreen extent -252,-252 252,252, body extent -252,-252 252,252, height 236
TRANS_NexFET_Q5A [mm] "TI recommended land pattern (nominal) M0139-01"
  rect 0.75x0.675 smd paste-0.1 mask+0.051: 1(-2.776,1.917) 2(-2.776,0.639) 3(-2.776,-0.639) 4(-2.776,-1.917)
  rect 0.655x0.675 smd paste-0.1 mask+0.051: 5(2.776,-1.917) 6(2.776,-0.639) 7(2.776,0.639) 8(2.776,1.917)
  rect 4.295x4.51 smd paste-2.2 mask+0.051: 9(0.301,0)
  silkscreen extent -3.4,-2.8 3.4,2.8, body extent -3.05,-2.5 3.05,2.5, height 1.11
WL-SMCW_GREEN [mm] "WURTH"
  rect 0.8x0.8 smd: 1(-0.8,0) 2(0.8,0)
  silkscreen extent -1.9,-0.8 1.2,0.8, body extent -0.85,-0.45 0.85,0.45, height 0.8

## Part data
C1: "CAP, AL, 150 μF, 50 V, +/- 20%, 0.18 ohm, SMD"
C2 C3: "CAP, CERM, 3.3 μF, 50 V, +/- 10%, X7R, 1210"
C4: "CAP, CERM, 0.033 μF, 50 V, +/- 10%, X7R, 0805"
C5 C12 C15 C21: "CAP, CERM, 0.1 μF, 25 V, +/- 10%, X7R, 0603"
C6: "CAP, AL, 100 μF, 35 V, +/- 20%, 0.34 ohm, SMD"
C7 C8 C9: "CAP, CERM, 22 μF, 25 V, +/- 10%, X7R, 1210"
C10 C11: "CAP, CERM, 0.22 μF, 25 V, +/- 10%, X7R, 0805"
C13: "CAP, CERM, 0.1 μF, 50 V, +/- 10%, X7R, 0805"
C14: "CAP, CERM, 0.18 μF, 25 V, +/- 10%, X7R, 0603"
C16: "CAP, CERM, 390 pF, 50 V, +/- 10%, X7R, 0603"
C17: "CAP, CERM, 100 pF, 50 V, +/- 5%, C0G/NP0, 0603"
C18: "CAP, CERM, 470 pF, 50 V, +/- 5%, C0G/NP0, AEC-Q200 Grade 1, 0603"
C19 C20: "CAP, CERM, 1 μF, 25 V, +/- 10%, X7R, 0805"
C22: "CAP, AL, 47 μF, 35 V, +/- 20%, 0.36 ohm, SMD"
C23 C24: "CAP, CERM, 10 μF, 25 V, +/- 10%, X7R, 0805"
C25 C26: "CAP, CERM, 4.7 μF, 25 V, +/- 10%, X7R, 0805"
C27 C28: "CAP, CERM, 0.047 μF, 25 V, +/- 10%, X7R, 0805"
C29 C30 C31: "CAP, CERM, 47 μF, 16 V, +/- 20%, X5R, 1210"
C32: "CAP, CERM, 47 pF, 50 V, +/- 5%, C0G/NP0, 0603"
C33: "CAP, CERM, 680 pF, 50 V, +/- 10%, X7R, 0603"
C34: "CAP, CERM, 4700 pF, 50 V, +/- 10%, X7R, AEC-Q200 Grade 1, 0603"
C35 C37 C38: "CAP, CERM, 0.1 μF, 50 V, +/- 10%, X7R, 0603"
C36: "CAP, CERM, 1 μF, 50 V, +/- 10%, X7R, 0805"
C39: "CAP, CERM, 2.2 μF, 50 V, +/- 10%, X7R, 0805"
C40 C41 C42 C43: "CAP, CERM, 10 μF, 50 V, +/- 10%, X7R, 1210"
D1: "Diode, Schottky, 60 V, 12 A, DPAK"
D2: "Diode, Schottky, 50 V, 0.2 A, SOD-523F"
D3: "Diode, Schottky, 100 V, 6 A, DPAK"
D4 D7: "Diode, Zener, 12 V, 300 mW, SOD-523"
D5 D6 D12: "LED, Green, SMD"
D8: "Diode, Schottky, 40 V, 12 A, DPAK"
D9: "Diode, Schottky, 35 V, 8 A, DPAK"
D10: "Diode, Schottky, 60 V, 7 A, DPAK"
D11: "Diode, TVS, Uni, 26 V, 600 W, SMB"
D13: "Diode, TVS, Uni, 14 V, 600 W, SMB"
FID1 FID2 FID3: "Fiducial mark.  There is nothing to buy or mount."
H1 H2 H3 H4: "Machine Screw, Round, #4-40 x 1/4, Nylon, Philips panhead"
H5 H6 H7 H8: "Standoff, Hex, 0.5\"L #4-40 Nylon"
J1 J3: "Header, 100mil, 2x1, Gold, TH"
J2 J4 J5 J6 J7 J8: "Terminal screw, vertical, snap-in"
L1: "Inductor, Drum Core, Ferrite, 12 μH, 6.3 A, 0.014 ohm, SMD"
L2 L4: "Inductor, Shielded Drum Core, Ferrite, 4.7 μH, 7 A, 0.01 ohm, SMD"
L3: "Inductor, Shielded Drum Core, Ferrite, 6.1 μH, 6.6 A, 0.017 ohm, AEC-Q200 Grade 1, SMD"
Logo2: library part EURoHS_Exempt
Logo3: library part FCC_disclaimer, "FCC_disclaimer"
NT1 NT2: "Single point connection between nets."
Q1 Q2 Q3: "MOSFET, N-CH, 60 V, 15 A, SON 5x6mm"
R1 R18 R28 R29: "RES, 0, 5%, 1.5 W, AEC-Q200 Grade 0, 2512"
R2: "RES, 33.2 k, 1%, 0.125 W, 0805"
R3: "RES, 10.0, 1%, 0.125 W, 0805"
R4: "RES, 100 k, 1%, 0.125 W, 0805"
R5: "RES, 71.5 k, 1%, 0.125 W, 0805"
R6 R10: "RES, 0, 5%, 0.1 W, 0603"
R7: "RES, 7.50 k, 1%, 0.1 W, 0603"
R8 R21: "RES, 16.9 k, 1%, 0.1 W, 0603"
R9: "RES, 0.015, 1%, 3 W, 2512"
R11 R16: "RES, 300, 5%, 0.25 W, 1206"
R12: "RES, 12 k, 5%, 0.125 W, 0805"
R13: "RES, 2.00 k, 1%, 0.125 W, 0805"
R14: "RES, 5.11 k, 1%, 0.1 W, 0603"
R15: "RES, 10.0, 1%, 0.1 W, 0603"
R17: "RES, 464, 1%, 0.1 W, 0603"
R19: "RES, 825 k, 1%, 0.125 W, 0805"
R20: "RES, 5.6, 5%, 0.25 W, 1206"
R22: "RES, 110 k, 1%, 0.125 W, 0805"
R23: "RES, 249 k, 1%, 0.1 W, 0603"
R24: "RES, 10.0 k, 1%, 0.1 W, 0603"
R25: "RES, 53.6 k, 1%, 0.1 W, 0603"
R26: "RES, 40.2, 1%, 0.1 W, 0603"
R27: "RES, 9.1 k, 5%, 0.125 W, 0805"
TP1 TP4 TP9 TP10 TP11 TP13 TP17 TP18 TP19: "Test Point, Compact, Red, TH"
TP2 TP3 TP6 TP7 TP8 TP12 TP16: "Test Point, Compact, Blue, TH"
TP15 TP20 TP21: "Test Point, Compact, Black, TH"
U1: "Wide Voltage Range Buck-Boost Controller, 20-pin TSSOP-EP, Pb-Free"
U2: "4.5 V to 42 V Input, 5 A, Step Down DC-DC Converter with Eco-mode?, DDA0008E"
U3: "Smart Diode Controller, DGK0008A"
ZZ1: library part AssemblyNoteLabel
ZZ2 ZZ3 ZZ4: library part AssemblyNote

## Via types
v1: diameter 30, hole 15, Top Layer to Bottom Layer, 210 vias
v2: diameter 19.68, hole 7.87, Top Layer to Bottom Layer, 12 vias
v3: diameter 19.68, hole 7.87, Top Layer to Bottom Layer, tented top, 6 vias

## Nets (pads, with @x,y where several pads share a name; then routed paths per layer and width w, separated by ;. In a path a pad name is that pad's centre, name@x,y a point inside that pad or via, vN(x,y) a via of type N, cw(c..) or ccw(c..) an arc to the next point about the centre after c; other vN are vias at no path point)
74610_GATE: Q3.4 U3.2 U3.5 U3.6 | length 474.2
  Top Layer w17: U3.5@725.55,2054.69 740.24,2040 v1(780,2040) ; v1(850,2000) 853.5,2003.5 U3.2@900.75,2003.5
  Top Layer w30: 710,2150 710,2100 725.55,2084.45 U3.5@725.55,2054.69
  3rd layer w40: v1(780,2040) 810,2040 v1(850,2000)
  2nd Layer w40: v1(780,2040) 810,2040 v1(850,2000)
  Bottom Layer w40: v1(780,2040) 810,2040 v1(850,2000)
ANODE: C37.1 D11.1 J6.1 J6.2 J6.3 J6.4 Q3.1 Q3.2 Q3.3 TP18.1 U3.3 U3.4 | length 1140.1
  Top Layer w30: D11.1@540,1927.01 577.01,1890
  Top Layer w40: 890,2040 900.89,2040 ; 900.75,2039.86 900.89,2040 ; 990,2040 900.89,2040
  Top Layer w50: 642.8,1840 652.8,1830 720,1830 730,1820 974.41,1820 974.41,1844.41 1000,1870 1000,2030 990,2040
  Top Layer w60: D11.1@540,1927.01 555.79,1927.01 642.8,1840
  Top Layer w120: D11.1@540,1940 540,2200 550,2210
BOOT_540: C21.2 U2.1 | length 308.6
  Top Layer w40: C21.2@850,1571.5 873.23,1571.5 891.73,1590 891.73,1618.27 v1(880,1630)
  3rd layer w40: v1(880,1630) 880,1601.73 v1@891.73,1590
  2nd Layer w40: v1(880,1630) 891.73,1618.27 v1@891.73,1590
  Bottom Layer w40: 907.28,1637.28 887.28,1637.28 v1(880,1630) 880,1601.73 891.73,1590 891.73,1604.02 899.37,1612.45 U2.1@915.5,1630.25
  other v1: 901.57,1589
CATHODE: C35.1 C36.1 C40.1 D10.4 L4.1 Q3.5 Q3.6 Q3.7 Q3.8 Q3.9 R27.2 U3.8 | length 573.3
  Top Layer w17: U3.8@725.55,1977.91 777.91,1977.91 820,2020 820,2228.14 Q3.9@831.86,2240
  Top Layer w40: 1161.5,1861.5 1200,1900 1200,2075.12 L4.1@1195.12,2080
  other v1: 780,2190 830,2190 880,2190 780,2240 830,2240 880,2240 780,2290 830,2290 880,2290 1551.02,2430 1620,2430 1690,2430 1551.02,2490.39 1620,2490.39 1690,2490.39 1551.02,2560 1620,2560 1690,2560 610,2680 710,2680 830,2680 930,2680 1050,2680 1170,2680 1310,2680 1470,2680 1620,2680 1730,2680
COMP_540: C32.1 R21.2 U2.6 | length 212.5
  Top Layer w40: v1(1020,1360) 1050,1360 1068.5,1341.5 R21.2@1068.5,1318.54 C32.1@1068.5,1250
  Bottom Layer w25: v1@1025,1365 U2.6@1025,1422.72
  Bottom Layer w30: v1(1020,1360) v1@1025,1365
COMP_5118: C14.2 C18.2 TP7.1 U1.9 | length 539.3
  Top Layer w14: U1.9@2410.67,1575.91 U1.9@2410.67,1609.33
  Top Layer w15: C18.2@2361.57,1718.5 2370.5,1709.58 2370.5,1649.5 U1.9@2410.67,1609.33
  Top Layer w40: C18.2@2361.57,1718.5 C14.2@2427.24,1718.5 2458.5,1718.5 v1(2460,1720)
  Bottom Layer w20: v1(2460,1720) 2520,1780 2520,1910 2490,1940 TP7.1@2490,1960
CS_5118: C17.1 R6.1 U1.12 | length 370.3
  Top Layer w13: 2410.67,1300.67 U1.12@2410.67,1351.5
  Top Layer w14: v1(2330,1270) 2350,1290 2400,1290 2410.67,1300.67
  Bottom Layer w20: R6.1@2287.4,1061.5 2295.91,1070 2295.91,1150 2295.91,1235.91 v1(2330,1270)
CSG_5118: C17.2 R10.1 U1.13 | length 341.4
  Top Layer w13: 2436.26,1286.26 U1.13@2436.26,1351.5
  Top Layer w14: v1(2380,1250) 2400,1250 2436.26,1286.26
  Bottom Layer w20: R10.1@2377.4,1061.5 2358.9,1080 2358.9,1150 2360,1151.1 2360,1230 v1(2380,1250)
DC_LINK: C1.1 C2.1 C3.1 C4.1 J1.1 Q1.5 Q1.6 Q1.7 Q1.8 Q1.9 R1.2 R2.2 R3.2 R4.2 R28.2 | length 466.8
  Top Layer w17: Q1.9@2810,1228.14 Q1.9@2821.86,1240
  2nd Layer w50: v1(3070,1200) v1(3070,1320)
  2nd Layer w60: v1(3070,1320) v1(3070,1430) v1(3070,1550) v1(3070,1650)
  other v1: 3070,830 3070,950 3070,1070 2770,1190 2820,1190 2870,1190 2770,1240 2820,1240 2870,1240 2770,1290 2820,1290 2870,1290
EN_540: R19.1 R22.2 U2.3 | length 326
  Bottom Layer w25: U2.3@1025,1637.28 R19.1@1025,1815
  Bottom Layer w30: R19.1@1040,1840 1100,1840 1120,1820 R22.2@1120,1760
EN_5118: R4.1 U1.4 | length 183.8
  Top Layer w13: U1.4@2538.62,1575.91 v1@2538.62,1631.38
  Bottom Layer w30: v1(2540,1640) 2610,1640 2620,1650 2620,1680 R4.1@2630,1690
FB_540: R24.2 R25.1 U2.5 | length 197.1
  Bottom Layer w25: R24.2@1075,1293.5 U2.5@1075,1422.72
  Bottom Layer w40: R24.2@1071.5,1290 1072,1289.5 1072,1271.3 1097.3,1246 R25.1@1110.5,1246
FB_5118: C18.1 R7.2 R14.2 R17.2 U1.8 | length 639.9
  Top Layer w13: U1.8@2436.26,1575.91 2436.26,1623.74
  Top Layer w15: v1(2420,1670) 2420,1640 2436.26,1623.74
  Top Layer w30: v1(2310,1720) 2310,1768.35 2321.65,1780 2360.08,1780 C18.1@2361.57,1781.5
  2nd Layer w40: v1(2310,1720) 2360,1670 v1(2420,1670)
  Bottom Layer w40: R14.2@2260,1678.5 2310,1678.5 ; R17.2@2330,1768.5 2310,1748.5 v1(2310,1720) 2310,1678.5 ; R7.2@2408.54,1718.5 2408.54,1681.46 v1@2411.5,1678.5 ; v1@2419.95,1670.05 v1@2411.5,1678.5 ; 2310,1678.5 v1@2411.5,1678.5
GND: C1.2 C2.2 C3.2 C4.2 C6.2 C7.2 C8.2 C9.2 C10.2 C11.2 C12.2 C13.2 C15.2 C16.2 C19.2 C20.2 C22.2 C23.2 C24.2 C25.2 C26.2 C27.2 C28.2 C29.2 C30.2 C31.2 C32.2 C33.2 C34.2 C35.2 C36.2 C38.2 C40.2 C41.2 C42.2 C43.2 D4.2 D5.1 D6.1 D7.2 D9.1 D9.3 D12.1 D13.1 J5.1 J5.2 J5.3 J5.4 J7.1 J7.2 J7.3 J7.4 NT1.2 Q2.1 Q2.2 Q2.3 R5.1 R8.1 R9.1 R17.1 R22.1 R23.1 R24.1 TP15.1 TP20.1 TP21.1 U1.6 U1.14 U1.21 U2.7 U2.9 | length 5356.2
  Top Layer w14: U1.14@2461.85,1351.5 2461.85,1425.32 U1.21@2500.24,1463.7 2487.44,1476.5 U1.6@2487.44,1575.91
  Top Layer w30: C34.2@1068.5,1420 1068.5,1528.5 1070,1530 ; Q2.1@2079.3,1144.51 Q2.2@2079.3,1194.84 Q2.3@2079.3,1245.16 ; 2079.3,1174.84 2253.51,1174.84 D7.2@2268.35,1160
  Top Layer w40: D12.1@488.5,2450 449.13,2450 410,2489.13 410,2550 480,2620 TP21.1@510,2620 ; v1(1530,1230) D5.1@1530,1268.5 ; D6.1@1580,98.5 1580,75.04 1595.04,60 v1(1640,60) ; v1(2384,597) 2398,583 v1(2398,485)
  Top Layer w50: 1070,1530 1190,1530 1229.84,1490.16 1229.84,1269.84 1210,1250 C32.2@1131.5,1250 ; R5.1@2526.61,1828.54 2526.61,1777.58 2537.2,1766.99
  3rd layer w40: v1@830,1720 v1(830,1760) ; v1(850,840) v1(930,840) ; v1(2033,65) v1(2441,65) 2514,65 2540,91 TP15.1@2540,100 ; 2040,1480 2040,1460 ; v1(2130,1140) v1(2180,1140) v1(2230,1140) ; v1(2182.99,1500) v1(2110,1500) ; v1(2230,1870) 2230,1860 v1(2250,1840) v1(2302.73,1840) v1(2370,1840) 2380,1850 v1(2430,1850) v1(2480,1850) 2520,1850 2540,1830 v1(2540,1750) ; v1(2384,597) 2397,584 v1(2397,538) 2398,537 v1(2398,485) ; v2(2559.29,1424.33) 2564.96,1430 v1(2630.16,1430) ; v1(2010,1460) 2040,1460 ; v1(2010,1460) v1(2040,1430) ; v1(2010,1460) 2010,1490 2020,1500 v1(2110,1500) ; v1(2040,1430) 2040,1460 ; v1(2040,1430) 2070,1460 ; 2040,1460 2070,1460 ; 2070,1460 v1(2110,1500)
  3rd layer w60: v1(1740,1930) 1740,1880 1770.15,1849.85 v1@2053.72,1849.85
  3rd layer w80: v1(2630.16,1430) v1(2720.08,1430) v1(2810,1430)
  2nd Layer w80: 2483,2266 2484,2267
  2nd Layer w100: 1543,1474 1799,1474 ; 1765,1508 1799,1474 ; 1945,1474 1799,1474
  2nd Layer w120: 2929,2233 2929,2321
  Bottom Layer w30: U2.7@975,1422.72 975,1313.98 998.98,1290 R24.1@1008.5,1290
  Bottom Layer w40: C27.2@860,1760 v1(830,1760) 830,1720 860,1720 C27.2@880,1740 ; U2.7@975,1422.72 975,1505 U2.9@1000,1530 ; v1(2630.16,1430) v1(2720.08,1430) v1(2810,1430)
  Bottom Layer w50: R9.1@2380,746.14 NT1.2@2380,860
  other v1: 2194,64 2113,66 2274,67 2359,67 1640,110 887,840 1044,1195 1088,1196 1132,1196 1176,1474 2029,1500 1143,1528 1110,1700 1160,1700 826,1718 1909.28,1843.15 1959.28,1843.15 2009.28,1843.15 2053,1843 1801,1849.85 1861,1849.85 1740,1890 2900,2220 2960,2220 3002,2220 3070,2220
  other v2: 2441.18,1424.33 2480.55,1424.33 2519.92,1424.33 2441.18,1463.7 2480.55,1463.7 2519.92,1463.7 2559.29,1463.7 2441.18,1503.07 2480.55,1503.07 2519.92,1503.07 2559.29,1503.07
  other v3: 948.82,1504.41 1000,1504.41 1051.18,1504.41 948.82,1555.59 1000,1555.59 1051.18,1555.59
HB_5118: C5.1 D2.1 U1.18 | length 171.3
  Top Layer w13: D2.1@2564.21,1264.29 U1.18@2564.21,1351.5
  Top Layer w25: D2.1@2563.46,1272 2563.46,1195.04 C5.1@2568.5,1190
HO_5118: Q1.4 U1.19 | length 347.1
  Top Layer w13: 2589.8,1310.2 U1.19@2589.8,1351.5
  Top Layer w15: 2589.8,1310.2 v1(2610,1290)
  Top Layer w40: v1(2680,1100) 2700,1120 2700,1150
  Bottom Layer w40: v1(2610,1290) 2610,1170 v1(2680,1100)
LO_5118: Q2.4 U1.15 | length 540
  Top Layer w13: 2487.44,1317.44 U1.15@2487.44,1351.5
  Top Layer w14: 2460,1270 2460,1290 2487.44,1317.44
  Top Layer w20: 2370,1200 2390,1200 2460,1270
  Top Layer w30: Q2.4@2079.3,1295.49 2134.51,1295.49 2190,1240 2281.46,1240 2320,1201.46 2368.54,1201.46
NetC14_1: C14.1 R7.1 | length 125.6
  Top Layer w30: C14.1@2427.24,1781.5 2458.67,1781.5 v1(2474.25,1797.07)
  Bottom Layer w40: R7.1@2408.54,1781.5 2458.67,1781.5 v1(2474.25,1797.07)
NetC23_1: C23.1 D8.4 L2.1 TP10.1
  other v1: 520,880 590,880 658.98,880 520,949.61 590,949.61 658.98,949.61 520,1010 590,1010 658.98,1010
NetC33_1: C33.1 R20.1 | length 88
  Bottom Layer w60: R20.1@612.91,1400 C33.1@612.91,1488
NetC34_1: C34.1 R21.1 | length 101.5
  Top Layer w40: R21.1@1131.5,1318.54 C34.1@1131.5,1420
NetC37_2: C37.2 C38.1 | length 79.1
  Top Layer w40: 668.5,1690 668.5,1767.01 C37.2@670,1768.5
NetC39_1: C39.1 U3.7 | length 369.5
  Top Layer w17: U3.7@725.55,2003.5 673.5,2003.5 660,1990 660,1940 680,1920 749.45,1920 C39.1@773.15,1896.3
  Top Layer w50: 670,1930 703.7,1896.3 C39.1@773.15,1896.3
NetC39_2: C39.2 U3.1 | length 193
  Top Layer w17: C39.2@853.15,1896.3 856.3,1896.3 880,1920 910,1920 ; U3.1@900.75,1977.91 U3.1@922.09,1977.91
  Top Layer w50: C39.2@856.3,1896.3 886.3,1896.3 910,1920 910,1952.89 910,1961.5
NetD3_1: D3.1 D3.3 NT2.2 R9.2 | length 357.7
  3rd layer w50: v1(2330,550) v1(2330,500) 2330,465 v1(2331,464)
  2nd Layer w50: v1(2330,550) v1(2330,500) 2330,465 v1(2331,464)
  Bottom Layer w50: 2230,700 2290,760 NT2.2@2290,860
NetD5_2: D5.2 R12.1 | length 80
  Top Layer w60: D5.2@1530,1340 R12.1@1530,1420
NetD6_2: D6.2 R13.1 | length 60
  Top Layer w60: 1580,180 R13.1@1580,240
NetD11_2: D11.2 D13.2 | length 133
  Top Layer w120: D13.2@514,1644.01 D11.2@514,1777
NetD12_2: D12.2 R27.1 | length 105.1
  Top Layer w50: D12.2@551.5,2450 591.5,2410 R27.1@640,2410
NetNT1_1: NT1.1 R10.2 | length 75.9
  Bottom Layer w20: NT1.1@2380,920 R10.2@2380,995.91
NetNT2_1: NT2.1 R6.2 | length 79.6
  Bottom Layer w20: R6.2@2287.4,998.5 2290,995.91 NT2.1@2290,920
NetR8_2: R8.2 U1.3 | length 117.7
  Top Layer w13: U1.3@2564.21,1575.91 2564.21,1615.33
  Top Layer w14: 2564.21,1615.33 2569.5,1620.61 2569.5,1676.55 R8.2@2580,1687.05
NetR14_1: R14.1 R15.1 TP8.1 | length 272.4
  Top Layer w40: v1(2210,1750) 2211.5,1751.5 R15.1@2260,1751.5
  Top Layer w50: TP8.1@2130,1760 2200,1760 v1(2210,1750)
  3rd layer w20: TP8.1@2130,1760 2200,1760 v1(2210,1750)
  Bottom Layer w40: v1(2210,1750) 2251.5,1750 R14.1@2260,1741.5
NetR25_2: R25.2 R26.1 TP16.1 | length 621.1
  Top Layer w30: v1(1220,1190) 1252.5,1190 1260,1182.5 1341.5,1182.5 1366,1158 1457,1158 1485,1186 1604,1186 TP16.1@1660,1130
  Bottom Layer w50: R25.2@1173.5,1239 R26.1@1266.5,1239 ; v1(1220,1190) 1220,1230
RAMP_5118: C16.1 U1.5 | length 120.7
  Top Layer w13: U1.5@2513.03,1575.91 2513.03,1616.97
  Top Layer w15: C16.1@2510,1687.05 2500,1677.05 2500,1630 2513.03,1616.97
RT_540: R23.2 U2.4 | length 62.1
  Bottom Layer w40: U2.4@1084,1641.5 R23.2@1146.14,1641.5
SS_5118: C15.1 U1.7 | length 116.6
  Top Layer w13: U1.7@2461.85,1575.91 v1@2461.85,1638.15
  Top Layer w15: v1@2460,1640 v1@2461.85,1638.15
  Bottom Layer w40: v1@2463.54,1646.46 2480,1630 C15.1@2480,1601.5
  other v1: 2460,1650
SW1_5118: C5.2 D3.4 L1.1 Q1.1 Q1.2 Q1.3 TP2.1 U1.20 | length 594.4
  Top Layer w15: U1.20@2616,1351.5 2686.93,1351.5 2700,1338.43 2700,1215.53 Q1.3@2700.7,1214.84
  Top Layer w30: C5.2@2641.5,1200 2656.33,1214.84 Q1.3@2700.7,1214.84
  Top Layer w40: 2560,903.86 2610,953.86 2610,1140 2631.5,1161.5 C5.2@2631.5,1190
  other v1: 2667,610 2603,611 2544,612 2502.02,686 2572.02,686 2641,686 2502.02,755.61 2572.02,755.61 2641,755.61 2502.02,816 2572.02,816 2641,816 2686,903 2586,962 2661,962 2471,963 2530,963 2473,1015 2526,1037 2591,1037 2660,1038
SW2_5118: D1.1 D1.3 L1.2 Q2.5 Q2.6 Q2.7 Q2.8 Q2.9 TP3.1 | length 259
  Top Layer w17: Q2.9@1950,1208.14 Q2.9@1961.86,1220
  2nd Layer w50: 2016,1069 2019,1066 v1(2019,953)
  Bottom Layer w50: TP3.1@1906,210 1906,335
  other v1: 1931,721 1988,743 2025,774 2020,996 2022,1035 1910,1170 1960,1170 2010,1170 1910,1220 1960,1220 2010,1220 1910,1270 1960,1270 2010,1270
